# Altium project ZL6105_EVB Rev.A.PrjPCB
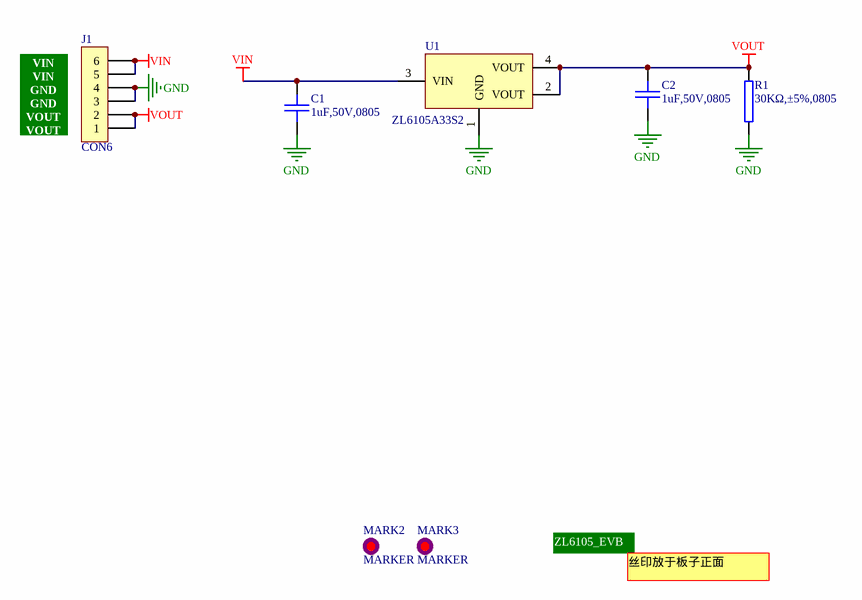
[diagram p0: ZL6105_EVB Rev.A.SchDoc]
1 sheet, 7 parts. Net scope: global (net labels, ports and power ports of the same name join across sheets).
Board file: ZL6105_EVB Rev.A单板.PcbDoc

## Sheet ZL6105_EVB Rev.A.SchDoc
size A4; CheckedBy: <审核日期>; Author: 谭国辉; CompanyName: 广州立功科技股份有限公司; DocumentNumber: 1; SheetNumber: 1; SheetTotal: 1; PageSetup: Record=PageOptions|CenterHorizontal=True|CenterVertical=True|PrintScale=1.00|XCorrection=1.00|YCorrection=1.00|PrintKind=0|BorderSize=5000000|LeftOffset=0|BottomOffset=0|Orientation=2|PaperLength=1000|PaperWidth=1000|Scale=100|PaperSource=7|PrintQuality=600|MediaType=1|DitherType=10|PaperKind=A4|PrintScaleMode=1; DesignDate: 2019-12-17; CheckDate: <审核人员>; SheetName: ZL6105_EVB Rev.A; SheetVersion: Rev.A; SheetDescription: ZL6105评估板

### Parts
C1  1uF,50V,0805  [0805C]
C2  1uF,50V,0805  [0805C]
J1  CON6  [SIP-6-2.54]
MARK2  MARKER  [MARKER-C-0.8M]  (no BOM)
MARK3  MARKER  [MARKER-C-0.8M]  (no BOM)
R1  30KΩ,±5%,0805  [0805R]
U1  ZL6105A33S2  [SOT229P700X180-4N]

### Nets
GND: C1.2 C2.2 J1.3 J1.4 R1.1 U1.1(GND)
VIN: C1.1 J1.5 J1.6 U1.3(VIN)
VOUT: C2.1 J1.1 J1.2 R1.2 U1.2(VOUT) U1.4(VOUT)

Not connected (* = marked no-connect by the designer): MARK2 0; MARK3 0

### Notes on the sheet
- (near J1) VIN
  VIN
  GND
  GND
  VOUT
  VOUT
- ZL6105_EVB
- 丝印放于板子正面

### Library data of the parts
C1 C2 = 02.01.00040: C2012X7R1H105KT000N ,0805,TDK,1uF,X7R,±10%,50V,; 旧物料代码: 1.02.02.0065; 名称: 电容; 封装: 0805; 贴片和直插: SMT; 器件优选方案: 不推荐使用
J1 = CON6: Connector
R1 = 01.01.00305: RTT05303JTP,0805,RALEC,30KΩ,±5%,1/8W,; 旧物料代码: 1.01.02.0083; 名称: 电阻; 封装: 0805; 贴片和直插: SMT; 器件优选方案: 通用物料
U1 = 89.12.00022: 名称: 集成电路; 厂商: ZHIYUAN; 贴片和直插: SMT; PCB备注: 200102ZW; 器件优选方案: 待导入物料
